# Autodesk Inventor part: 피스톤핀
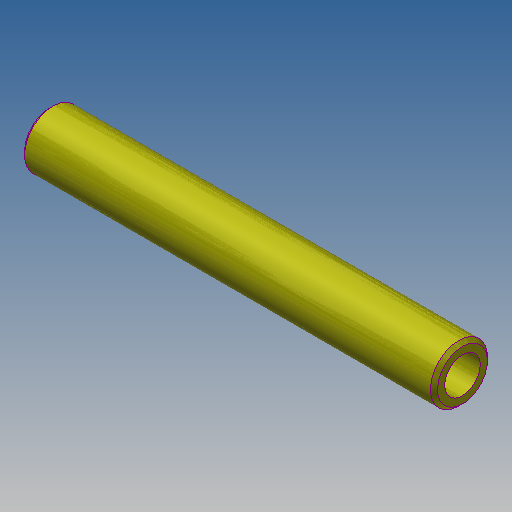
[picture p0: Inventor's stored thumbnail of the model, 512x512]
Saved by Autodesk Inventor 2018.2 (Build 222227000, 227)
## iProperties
Created: 2016-11
Part Number: 피스톤핀
Material: 강철, 탄소
Document SubType Name: Modeling
Designer: mduedu
Density: 7.87 g/cm^3
Mass: 13.9342 g
Surface Area: 24.1465 cm^2
Volume: 1.77055 cm^3
Appearance: 노란색
Author: mduedu
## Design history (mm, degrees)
sketch "스케치1"
  geometry: C1 r 2.5 at (0, 0); C2 r 4 at (0, 0); 1 further point
  constraints: 2 centre point, 2 coincident
  dimensions: "d0" = 5 diameter of C1; "d1" = 8 diameter of C2
extrude "돌출1" new body sketch "스케치1" stored distance "d2" = 58; taper "d3" = 0 deg
chamfer "모따기1" distance "d4" = 0.5; stored, may be unused: second distance "d5" = 2, angle "d6" = 45 deg
node "솔리드1"
